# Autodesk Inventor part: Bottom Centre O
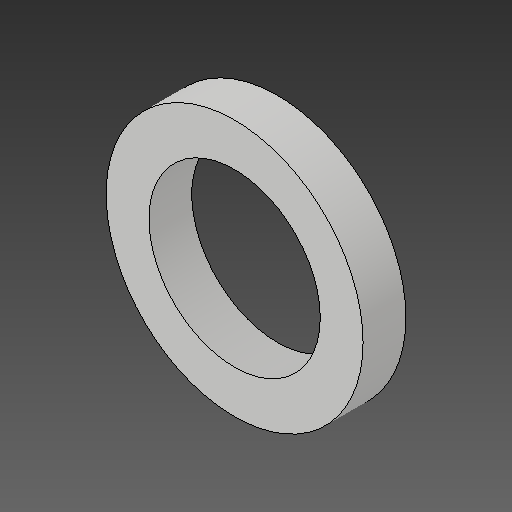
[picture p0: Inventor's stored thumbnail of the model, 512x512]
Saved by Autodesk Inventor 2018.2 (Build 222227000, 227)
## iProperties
Created: 2018-03
Part Number: Bottom Centre O
Material: Generic
Document SubType Name: Modeling
Designer: PeterMaxwell-Stewart
Mass: 1.9635 g
Surface Area: 15.708 cm^2
Volume: 1.9635 cm^3
Density: 1 g/cm^3
Appearance: Default
Author: PeterMaxwell-Stewart
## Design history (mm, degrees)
derived "O's and X's.ipt"
feature "Bottom Centre O::O's and X's.ipt" dims "d0" = 10
tag "TaggingFeature1"
body "Solid1"
